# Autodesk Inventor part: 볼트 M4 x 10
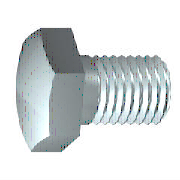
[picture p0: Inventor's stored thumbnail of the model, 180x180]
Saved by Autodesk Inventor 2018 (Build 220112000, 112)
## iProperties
Created: 2012-02
Part Number: 볼트 M4 x 10
Material: 스테인리스강
Description: 6각 머리 나사
Document SubType Name: Modeling
Standard: ISO 4017
Designer: mduedu
Standard Revision: Third edition 1999-08-15
Standards Organization: ISO
Language: ko-KR
Size Designation: M4 x 10
Categories: <MemberInstance><Categories><Category DisplayName="조임쇠" InternalName="e4da775c-781d-43d5-af7c-5136215cf5a6" Mnemonic="FSTN"><Category DisplayName="볼트" InternalN
Density: 8.08 g/cm^3
Appearance: 반광택
IsCustomPart: 0
Author: mduedu
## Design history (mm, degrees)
sketch "스케치1"
  geometry: L1 (0, 3.015)-(0, 2); L2 (2.1, 2)-(10, 2); L3 (10, 2)-(10, 0); L4 (10, 0)-(-0.4, 0); L5 (-2.48, 0)-(12.08, 0) reference; L6 (-0.4, 0)-(-0.4, 3.015); L7 (-0.4, 3.015)-(0, 3.015); L8 (2.1, 2)-(1.67, 2); L9 (1.67, 2)-(0, 2); L10 (0, -0.603)-(0, 3.618) reference
  constraints: 16 end point, 2 collinear, 2 perpendicular, 1 parallel
  dimensions: "d0" = 10 distance between parallel lines of L3 L1 (= NLG); "d1" = 7.9 distance from line of L2.start L3 (= GEL); "d2" = 4 diameter of L2 L4 (= GD); "d9" = 0.4001 distance between parallel lines of L6 L1 (computed from SD); "d10" = 6.03 diameter of L7 L4 (= SD2); "d13" = 0.42952 distance of L2.start L8.end (computed from GAL); "d14" = 4 diameter of L9 L4 (= BDM)
revolve "본체" sketch "스케치1" stored, may be unused: angle "d12" = 90 deg
sketch "스케치2"
  geometry: L1 (0, 4.041)-(3.5, 2.021); L2 (3.5, 2.021)-(3.5, -2.021); L3 (3.5, -2.021)-(0, -4.041); L4 (0, -4.041)-(-3.5, -2.021); L5 (-3.5, -2.021)-(-3.5, 2.021); L6 (-3.5, 2.021)-(0, 4.041); 2 further points
  constraints: 12 end point, 1 coincident, 1 vertical, 11 other
  dimensions: "d11" = 7 distance between parallel lines of L5 L2 (= SW)
extrude "머리" join sketch "스케치2" distance "d3" = 2.4 (= KOH - SD); taper "d4" = 0 deg
sketch "스케치4"
  geometry: L1 (-2.8, 3.5)-(-2.8, 4.041); L2 (-2.8, 4.041)-(-2.487, 4.041); L3 (-2.487, 4.041)-(-2.8, 3.5); L4 (-3.28, 0)-(0.08, 0) reference; L5 (-0.4, 4.041)-(-2.8, 4.041) reference; L6 (-2.8, 2.021)-(-2.8, 4.041) reference
  constraints: 6 end point, 2 collinear, 1 perpendicular, 1 vertical
  dimensions: "d5" = 30 deg angle of L3 L1 (= ANG1); "d19" = 7 diameter of L1.start L4 (= SW0)
revolve "모따기1" sketch "스케치4" stored, may be unused: angle "d21" = 90 deg
workplane "Work Plane1"
body "Solid1"
feature "스레드" dims "d15" = 7.9 (= GEL), "d16" = 0
chamfer "모따기2" distance "d6" = 0.42941 (= -0.5 x SPD + 0.5 x GD); stored, may be unused: second distance "d7" = 0.42952 (computed from GUL), angle "d55" = 45 deg
other parameters: "NLG" = 10 [user parameter; used in 1 equation term], "GD" = 4 (= NND) [user parameter; used in 2 equation terms], "BDM" = 4 (= NND) [user parameter; used in 1 equation term], "KOH" = 2.8 [user parameter; used in 1 equation term], "GEL" = 7.9 [user parameter; used in 2 equation terms], "SW" = 7 [user parameter; used in 2 equation terms], "SW0" = 7 (= SW) [user parameter; used in 1 equation term], "SPD" = 3.14117 (= NND - 1.2269 x PTC) [user parameter; used in 1 equation term], "SD2" = 6.03 [user parameter; used in 2 equation terms], "SD" = 0.4 [user parameter; used in 2 equation terms], "ANG1" = 30 deg [user parameter; used in 1 equation term], "GAL" = 0.42941 (= 0.61345 x PTC) [user parameter; used in 1 equation term], "GUL" = 0.42941 (= 0.61345 x PTC) [user parameter; used in 1 equation term], "d8" = 0, "RR" = 0.2 [user parameter], "d57" = 0, "d58" = 0, "TPU" = 14.28571 (computed from PTC) [user parameter], "GD1" = 3.14117 (= THREADDIA - 1.2269 x PTC) [user parameter], "THREADDIA" = 4 [user parameter; used in 1 equation term], "SDH" = 6.03 (= SD2) [user parameter], "SDHG" = 2.1 [user parameter], "TOA" = 30 deg [user parameter], "PTC" = 0.7 [user parameter; used in 5 equation terms], "NND" = 4 [user parameter; used in 3 equation terms], "E0" = 8.085 [user parameter]
